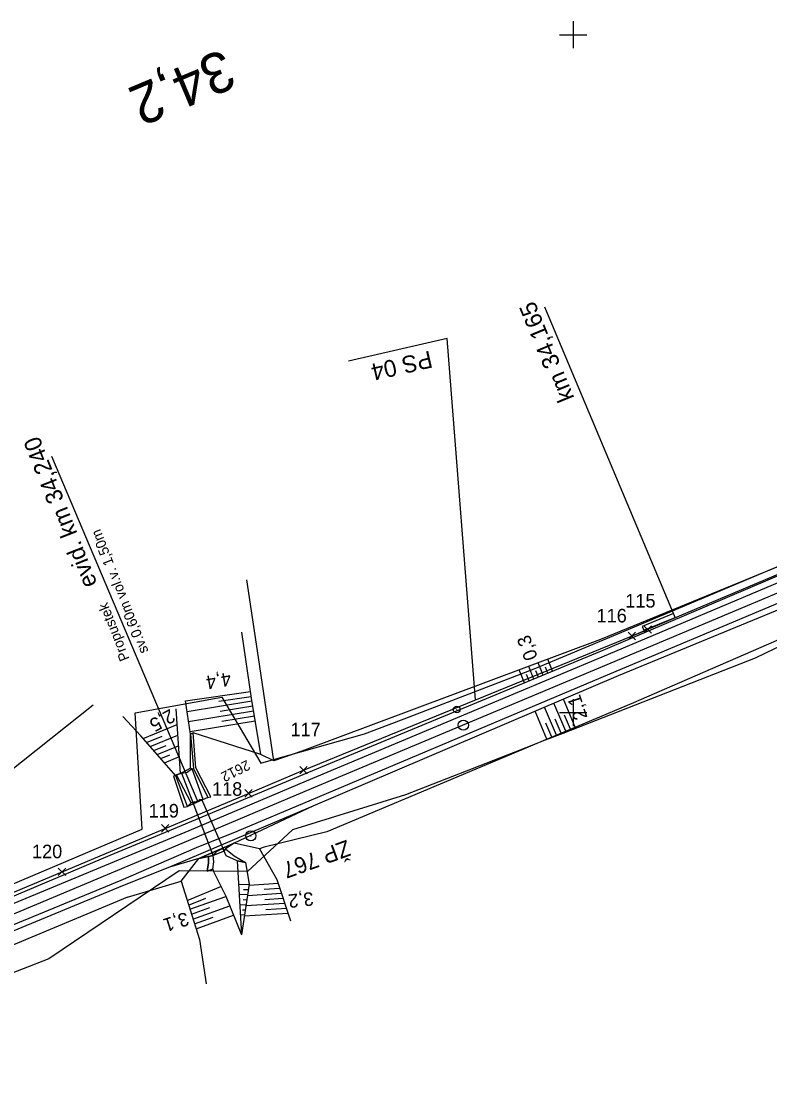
# Model space of a CAD drawing. Extents: x -805730 to -804640, y -1150889 to -1150366.
# Drawn here: x -805081.4 to -804971, y -1150654 to -1150498 of the extents above; entities that cross this region are included whole.
import ezdxf

# ---------------------------------------------------------------- set-up
doc = ezdxf.new("R2010")
doc.units = 0
for name, color, linetype in [('0381KM032-037P - Vrstva 1', 7, 'Continuous'), ('0381KM032-037P - Vrstva 16', 7, 'Continuous'), ('0381KM032-037P - Vrstva 17', 7, 'Continuous'), ('0381KM032-037P - Vrstva 19', 7, 'Continuous'), ('0381KM032-037P - Vrstva 4', 7, 'Continuous'), ('0381KM032-037P - Vrstva 48', 7, 'Continuous'), ('0381KM032-037P - Vrstva 49', 7, 'Continuous'), ('0381KM032-037P - Vrstva 57', 7, 'Continuous'), ('0381KM032-037P - Vrstva 7', 7, 'Continuous'), ('0381KM032-037P - Vrstva 9', 7, 'Continuous'), ('Default', 7, 'Continuous'), ('hran DP - hran DP', 7, 'Continuous'), ('krizky_1000 - Vrstva 1', 7, 'Continuous'), ('PSR_C2_2_Lomove_body_Vimperk - Vrstva 60', 7, 'Continuous'), ('PSR_C2_2_trasa_Vimperk - Kabelová trasa', 7, 'Continuous'), ('SOPS', 7, 'Continuous'), ('vyt_sit - stávající', 7, 'Continuous')]:
    doc.layers.add(name, color=color, linetype=linetype)

msp = doc.modelspace()

# ---------------------------------------------------------------- linework, layer by layer
at = {"layer": '0381KM032-037P - Vrstva 1'}
for points in [[(-804910.33, -1150557.31), (-804952.12, -1150574.92), (-804994.42, -1150592.71), (-805038.63, -1150611.27), (-805057.71, -1150619.3), (-805074.24, -1150626.27)], [(-805074.24, -1150626.27), (-805091.51, -1150633.48)]]:
    msp.add_lwpolyline(points, dxfattribs=at)
at = {"layer": '0381KM032-037P - Vrstva 16'}
for points in [[(-805053.78, -1150621.21), (-805053.78, -1150622.18), (-805053.99, -1150623.39), (-805053.13, -1150623.09), (-805053, -1150622.04), (-805053.1, -1150621.07), (-805053.78, -1150621.21)], [(-805051.5, -1150620.47), (-805051.28, -1150620.09), (-805050.01, -1150621.11), (-805048.33, -1150622.13), (-805049.58, -1150621.86), (-805051.2, -1150621.14), (-805051.5, -1150620.47)]]:
    msp.add_lwpolyline(points, dxfattribs=at)
at = {"layer": '0381KM032-037P - Vrstva 17'}
for points in [[(-804868.16, -1150549.89), (-804869.02, -1150549.09), (-804889.78, -1150557.12), (-804908.89, -1150563.18), (-804949.8, -1150580.61), (-804991.45, -1150598.69), (-805036.34, -1150617.58)], [(-804906.51, -1150551), (-804923.2, -1150557.6), (-804942.52, -1150566.83), (-804953.3, -1150571.71), (-804995.99, -1150589.23), (-805040.03, -1150605.68), (-805044.15, -1150607.13)], [(-805044.15, -1150607.13), (-805046.42, -1150591.86), (-805048.16, -1150580.41)], [(-805070.8, -1150598.9), (-805121.06, -1150638.84), (-805152.76, -1150646.7), (-805170.92, -1150650.08), (-805194.39, -1150650.05), (-805213.2, -1150651.26), (-805221.79, -1150652.33), (-805228.79, -1150654.03)]]:
    msp.add_lwpolyline(points, dxfattribs=at)
at = {"layer": '0381KM032-037P - Vrstva 19'}
for p, q in [((-805076.95, -1150562.18), (-805055.39, -1150613.19)), ((-805056.34, -1150613.34), (-805058.5, -1150609.19)), ((-805054.78, -1150612.85), (-805056.06, -1150613.31)), ((-805053.1, -1150621.07), (-805056.06, -1150613.31)), ((-805054.78, -1150612.85), (-805051.5, -1150620.47)), ((-805051.5, -1150620.47), (-805053.1, -1150621.07))]:
    msp.add_line(p, q, dxfattribs=at)
for points in [[(-805056.22, -1150608.31), (-805056.45, -1150608.2), (-805056.44, -1150603.21)], [(-805053.89, -1150612.54), (-805053.47, -1150612.44), (-805055.64, -1150608.13), (-805056.05, -1150602.98), (-805056.44, -1150603.21), (-805056.02, -1150608.26)], [(-805056.45, -1150608.2), (-805056.99, -1150608.48), (-805057.93, -1150608.98), (-805058.5, -1150609.19)], [(-805054.6, -1150612.84), (-805056.22, -1150608.31), (-805056.92, -1150608.82), (-805057.71, -1150609)], [(-805056.22, -1150608.31), (-805056.02, -1150608.26), (-805053.89, -1150612.54), (-805056.9, -1150613.84)], [(-805056.06, -1150613.31), (-805057.71, -1150609), (-805058.5, -1150609.19), (-805058.59, -1150609.33), (-805058.96, -1150609.37), (-805057.41, -1150613.95), (-805056.9, -1150613.84), (-805058.59, -1150609.33)], [(-805055.86, -1150613.18), (-805056.06, -1150613.31), (-805056.34, -1150613.34), (-805056.9, -1150613.84)], [(-805054.6, -1150612.84), (-805054.78, -1150612.85), (-805055.1, -1150612.83)], [(-805055.21, -1150621.51), (-805053.78, -1150621.21), (-805055.21, -1150621.51), (-805050.01, -1150619.25), (-805051.28, -1150620.09), (-805051.5, -1150620.47), (-805051.69, -1150620.12)], [(-805053.78, -1150621.21), (-805053.1, -1150621.07), (-805052.93, -1150620.83)]]:
    msp.add_lwpolyline(points, dxfattribs=at)
for centre, major_axis, ratio, start_param, end_param in [((-805055.48, -1150613.01), (0.389, 0.172), 0.155868, 3.060843, 6.493994), ((-805052.24, -1150620.62), (-0.751, -0.434), 0.315901, 3.723079, 5.657425)]:
    msp.add_ellipse(centre, major_axis=major_axis, ratio=ratio, start_param=start_param, end_param=end_param, dxfattribs=at)
at = {"layer": '0381KM032-037P - Vrstva 4'}
for points in [[(-804864.42, -1150538.53), (-804893.06, -1150548.77), (-804911.6, -1150556.2), (-804952.82, -1150573.68), (-804994.86, -1150591.44), (-805039.39, -1150610.13), (-805056.71, -1150617.44), (-805097.6, -1150634.39)], [(-804872.17, -1150539.66), (-804893.72, -1150547.52), (-804911.96, -1150555), (-804952.93, -1150572.63), (-804995.29, -1150590.69), (-805039.86, -1150609.18), (-805057.83, -1150616.69), (-805068.36, -1150621.07), (-805097.92, -1150633.57)], [(-804862.73, -1150542.41), (-804863.39, -1150541.46), (-804892.29, -1150551.48), (-804910.22, -1150558.86), (-804951.61, -1150576.23), (-804993.7, -1150593.96), (-805038.63, -1150612.92), (-805049.62, -1150617.53), (-805055.59, -1150619.94), (-805066.74, -1150624.75), (-805096.44, -1150637.01)], [(-804864.94, -1150543.15), (-804869.59, -1150544.8), (-804891.93, -1150552.26), (-804909.8, -1150559.87), (-804951.24, -1150577.2), (-804993.38, -1150594.6), (-805038.39, -1150613.8), (-805059.54, -1150622.79), (-805066.49, -1150625.57), (-805096.25, -1150637.87)]]:
    msp.add_lwpolyline(points, dxfattribs=at)
at = {"layer": '0381KM032-037P - Vrstva 48'}
for p, q in [((-805004.43, -1150594.48), (-805005.15, -1150592.66)), ((-805003.04, -1150593.91), (-805003.74, -1150592.13)), ((-805007.2, -1150595.63), (-805007.96, -1150593.7)), ((-805006.51, -1150595.34), (-805006.88, -1150594.39)), ((-805005.82, -1150595.05), (-805006.56, -1150593.18)), ((-805005.12, -1150594.77), (-805005.49, -1150593.84)), ((-805003.74, -1150594.19), (-805004.09, -1150593.29)), ((-805047.61, -1150596.92), (-805057.19, -1150598.31)), ((-805047.5, -1150597.67), (-805052.29, -1150598.36)), ((-805047.4, -1150598.32), (-805056.95, -1150599.89)), ((-805047.27, -1150599.06), (-805052.05, -1150599.84)), ((-805002.47, -1150603.33), (-805004.21, -1150599.21)), ((-805001.09, -1150602.75), (-805002.83, -1150598.63)), ((-804999.71, -1150602.17), (-805001.45, -1150598.04)), ((-805047.15, -1150599.8), (-805056.72, -1150601.37)), ((-805047.02, -1150600.54), (-805051.82, -1150601.32)), ((-805003.86, -1150603.91), (-805005.59, -1150599.8)), ((-805000.4, -1150602.46), (-805001.27, -1150600.4)), ((-805063.45, -1150603.82), (-805058.4, -1150601.75)), ((-805046.9, -1150601.28), (-805056.5, -1150602.85)), ((-805003.17, -1150603.62), (-805004.03, -1150601.56)), ((-805001.78, -1150603.04), (-805002.65, -1150600.98)), ((-805062.93, -1150604.42), (-805060.64, -1150603.48)), ((-805062.4, -1150605.02), (-805058.3, -1150603.33)), ((-805061.88, -1150605.61), (-805060.06, -1150604.86)), ((-805061.35, -1150606.21), (-805058.2, -1150604.91)), ((-805060.83, -1150606.8), (-805059.49, -1150606.25)), ((-805060.3, -1150607.4), (-805058.09, -1150606.49)), ((-805056.95, -1150627.71), (-805051.95, -1150625.67)), ((-805047.79, -1150625.42), (-805049.38, -1150625.34)), ((-805043.49, -1150625.24), (-805047.8, -1150625.5)), ((-805056.72, -1150628.43), (-805054.17, -1150627.38)), ((-805056.53, -1150629.02), (-805051.22, -1150627.12)), ((-805048.02, -1150626.91), (-805049.29, -1150626.85)), ((-805047.91, -1150626.17), (-805048.62, -1150626.13)), ((-805043.02, -1150626.71), (-805048.04, -1150627.02)), ((-805043.25, -1150625.97), (-805045.59, -1150626.11)), ((-805042.78, -1150627.45), (-805045.47, -1150627.61)), ((-805056.31, -1150629.74), (-805053.62, -1150628.78)), ((-805056.08, -1150630.46), (-805050.66, -1150628.52)), ((-805048.26, -1150628.4), (-805049.2, -1150628.36)), ((-805048.14, -1150627.66), (-805048.69, -1150627.63)), ((-805042.54, -1150628.18), (-805048.28, -1150628.53)), ((-805042.3, -1150628.92), (-805045.35, -1150629.11)), ((-805055.86, -1150631.17), (-805053.12, -1150630.19)), ((-805055.63, -1150631.89), (-805050.1, -1150629.91)), ((-805048.49, -1150629.89), (-805049.11, -1150629.86)), ((-805048.37, -1150629.15), (-805048.77, -1150629.13)), ((-805042.06, -1150629.66), (-805048.51, -1150630.05))]:
    msp.add_line(p, q, dxfattribs=at)
at = {"layer": '0381KM032-037P - Vrstva 49'}
for p, q in [((-805056.44, -1150603.21), (-805057.2, -1150598.28)), ((-805057.93, -1150608.98), (-805058.55, -1150599.44)), ((-805056.05, -1150602.98), (-805056.44, -1150603.21)), ((-805044.15, -1150607.13), (-805046.07, -1150606.17)), ((-805049.58, -1150621.86), (-805048.94, -1150632.8)), ((-805049.58, -1150621.86), (-805048.33, -1150622.13))]:
    msp.add_line(p, q, dxfattribs=at)
for points in [[(-804871.36, -1150538.86), (-804872.17, -1150539.66), (-804893.72, -1150547.52), (-804911.96, -1150555), (-804952.93, -1150572.63), (-804995.29, -1150590.69), (-805039.86, -1150609.18), (-805057.83, -1150616.69), (-805068.36, -1150621.07), (-805097.92, -1150633.57)], [(-804906.51, -1150551), (-804923.2, -1150557.6), (-804942.52, -1150566.83), (-804953.3, -1150571.71), (-804995.99, -1150589.23), (-805040.03, -1150605.68), (-805044.15, -1150607.13)], [(-804889.78, -1150557.12), (-804908.89, -1150563.18), (-804949.8, -1150580.61), (-804991.45, -1150598.69), (-805036.34, -1150617.58)], [(-804909.8, -1150559.87), (-804951.24, -1150577.2), (-804993.38, -1150594.6), (-805038.39, -1150613.8), (-805050.01, -1150619.25), (-805055.21, -1150621.51), (-805059.54, -1150622.79), (-805066.49, -1150625.57), (-805096.25, -1150637.87)], [(-805046.07, -1150606.17), (-805047.47, -1150597.89), (-805048.87, -1150588.15)], [(-805070.8, -1150598.9), (-805121.06, -1150638.84), (-805152.76, -1150646.7), (-805170.92, -1150650.08), (-805194.39, -1150650.05), (-805213.2, -1150651.26), (-805221.79, -1150652.33), (-805228.79, -1150654.03)], [(-805058.59, -1150609.33), (-805063.79, -1150603.44), (-805066.42, -1150600.59)], [(-805046.07, -1150606.17), (-805056.05, -1150602.98)], [(-805058.59, -1150609.33), (-805058.5, -1150609.19), (-805057.93, -1150608.98)], [(-805036.34, -1150617.58), (-805045.56, -1150619.85), (-805046.28, -1150620.1), (-805050.01, -1150619.25)], [(-805053.13, -1150623.09), (-805053.99, -1150623.39), (-805053.78, -1150622.18), (-805053.78, -1150621.21), (-805055.21, -1150621.51)], [(-805046.28, -1150620.1), (-805043.7, -1150624.61), (-805041.72, -1150630.72)], [(-805065.73, -1150627.22), (-805057.84, -1150624.88), (-805055.21, -1150621.51)], [(-805048.33, -1150622.13), (-805047.78, -1150625.31), (-805048.94, -1150632.8)], [(-805053.13, -1150623.09), (-805053.07, -1150623.46), (-805051.23, -1150627.1), (-805048.94, -1150632.8)], [(-805057.84, -1150624.88), (-805055.13, -1150633.48), (-805054.13, -1150640.03)], [(-805065.73, -1150627.22), (-805095.53, -1150639.67)]]:
    msp.add_lwpolyline(points, dxfattribs=at)
at = {"layer": '0381KM032-037P - Vrstva 7'}
msp.add_line((-805017.22, -1150599.55), (-805017.12, -1150599.55), dxfattribs=at)
for centre, radius in [((-805017.17, -1150599.55), 0.5), ((-805016.2, -1150601.85), 0.75)]:
    msp.add_circle(centre, radius, dxfattribs=at)
at = {"layer": '0381KM032-037P - Vrstva 9'}
for p, q in [((-805004.24, -1150540.13), (-804985.09, -1150585.68)), ((-804985.2, -1150585.4), (-804985.43, -1150584.85)), ((-804985.2, -1150585.4), (-804989.83, -1150587.31)), ((-804989.6, -1150587.86), (-804984.97, -1150585.96)), ((-804984.97, -1150585.96), (-804985.2, -1150585.4)), ((-804989.83, -1150587.31), (-804989.6, -1150587.86))]:
    msp.add_line(p, q, dxfattribs=at)
at = {"layer": 'hran DP - hran DP'}
for p, q in [((-804981, -1150583.16), (-804968.41, -1150577.86)), ((-804951.89, -1150581.61), (-804973.16, -1150591.99)), ((-804993.4, -1150588.37), (-804981, -1150583.16)), ((-805005.74, -1150593.57), (-804993.4, -1150588.37)), ((-804973.16, -1150591.99), (-805001.53, -1150603.08)), ((-805024.92, -1150600.92), (-805005.74, -1150593.57)), ((-805064.61, -1150600.03), (-805051.81, -1150597.72)), ((-805051.81, -1150597.72), (-805046.06, -1150607.46)), ((-805063.58, -1150617.18), (-805064.61, -1150600.03)), ((-805030.76, -1150603.16), (-805024.92, -1150600.92)), ((-805043.88, -1150606.84), (-805030.76, -1150603.16)), ((-805001.53, -1150603.08), (-805004.51, -1150604.24)), ((-805006.96, -1150605.2), (-805008.86, -1150605.94)), ((-805004.51, -1150604.24), (-805006.96, -1150605.2)), ((-805046.06, -1150607.46), (-805043.88, -1150606.84)), ((-805008.86, -1150605.94), (-805024.72, -1150612.14)), ((-805024.72, -1150612.14), (-805041.4, -1150617.28)), ((-805066.7, -1150618.51), (-805063.58, -1150617.18)), ((-805041.4, -1150617.28), (-805048.02, -1150623.43)), ((-805096.7, -1150631.27), (-805066.7, -1150618.51)), ((-805058.1, -1150623.37), (-805077.33, -1150636.32)), ((-805048.02, -1150623.43), (-805058.1, -1150623.37)), ((-805077.33, -1150636.32), (-805095.21, -1150643.26))]:
    msp.add_line(p, q, dxfattribs=at)
at = {"layer": 'krizky_1000 - Vrstva 1'}
for points in [[(-805000, -1150498), (-805000, -1150502)], [(-805002, -1150500), (-804998, -1150500)], [(-805000, -1150598), (-805000, -1150602)], [(-805002, -1150600), (-804998, -1150600)]]:
    msp.add_lwpolyline(points, dxfattribs=at)
at = {"layer": 'PSR_C2_2_Lomove_body_Vimperk - Vrstva 60'}
for p, q in [((-804991.9, -1150589.26), (-804990.8, -1150588.16)), ((-804990.8, -1150589.26), (-804991.9, -1150588.16)), ((-804989.56, -1150588.31), (-804988.46, -1150587.21)), ((-804988.46, -1150588.31), (-804989.56, -1150587.21)), ((-805040.34, -1150609.05), (-805039.24, -1150607.95)), ((-805039.24, -1150609.05), (-805040.34, -1150607.95)), ((-805048.45, -1150612.47), (-805047.35, -1150611.37)), ((-805047.35, -1150612.47), (-805048.45, -1150611.37)), ((-805060.72, -1150617.63), (-805059.62, -1150616.53)), ((-805059.62, -1150617.63), (-805060.72, -1150616.53)), ((-805075.95, -1150624.05), (-805074.85, -1150622.95)), ((-805074.85, -1150624.05), (-805075.95, -1150622.95))]:
    msp.add_line(p, q, dxfattribs=at)
at = {"layer": 'PSR_C2_2_trasa_Vimperk - Kabelová trasa'}
for points in [[(-804861.61, -1150536.05), (-804874.49, -1150540.07), (-804895.8, -1150547.79), (-804932.46, -1150563.38), (-804958.05, -1150574.66), (-804991.35, -1150588.71)], [(-805122.45, -1150641.59), (-805112.53, -1150638.37), (-805102.25, -1150634.46), (-805084.03, -1150627.11), (-805075.4, -1150623.5), (-805060.17, -1150617.08), (-805047.9, -1150611.92), (-805039.79, -1150608.5), (-804989.01, -1150587.76)]]:
    msp.add_lwpolyline(points, dxfattribs=at)
at = {"layer": 'SOPS'}
msp.add_lwpolyline([(-805014.4, -1150598.13), (-805018.6, -1150544.84), (-805033.13, -1150548.15)], dxfattribs=at)
at = {"layer": 'vyt_sit - stávající'}
msp.add_line((-805047.59, -1150618.19), (-805047.49, -1150618.19), dxfattribs=at)
msp.add_circle((-805047.55, -1150618.19), 0.756, dxfattribs=at)

# ---------------------------------------------------------------- texts
at = {"layer": '0381KM032-037P - Vrstva 19'}
for s, height, p in [('evid. km 34,240', 2.5, (-805070.16, -1150581.01)), ('sv.0,60m vol.v. 1,50m', 1.5, (-805062.62, -1150590.96)), ('Propustek', 1.5, (-805065.41, -1150592.06))]:
    msp.add_text(s, height=height, rotation=111.5275, dxfattribs=at).set_placement(p)
at = {"layer": '0381KM032-037P - Vrstva 48'}
for s, rotation, p in [('0,3', 110.4812, (-805005.19, -1150591.87)), ('4,4', 189.5991, (-805050.63, -1150594.02)), ('2,1', 108.1045, (-804997.87, -1150600.72)), ('2,5', 208.7064, (-805059.44, -1150599.4)), ('3,2', 186.1394, (-805038.41, -1150626.45)), ('3,1', 197.4468, (-805057.08, -1150629.39))]:
    msp.add_text(s, height=2, rotation=rotation, dxfattribs=at).set_placement(p)
at = {"layer": '0381KM032-037P - Vrstva 57'}
msp.add_text('2612', height=1.5, rotation=206.8307, dxfattribs=at).set_placement((-805048.13, -1150606.95))
at = {"layer": '0381KM032-037P - Vrstva 7'}
msp.add_text('34,2', height=6, rotation=202.7734, dxfattribs=at).set_placement((-805051.6, -1150502))
at = {"layer": '0381KM032-037P - Vrstva 9'}
msp.add_text('km 34,165', height=2.5, rotation=112.3772, dxfattribs=at).set_placement((-804999.79, -1150553.58))
at = {"layer": 'Default'}
for s, p in [('115', (-804992.31, -1150584.51)), ('116', (-804996.55, -1150586.7)), ('117', (-805041.7, -1150603.5)), ('118', (-805053.27, -1150612.28)), ('119', (-805062.62, -1150615.48)), ('120', (-805079.83, -1150621.49))]:
    msp.add_text(s, height=2, dxfattribs=at).set_placement(p)
at = {"layer": 'SOPS'}
msp.add_text('PS 04', height=2.5, rotation=192.874, dxfattribs=at).set_placement((-805021.12, -1150546.6))
at = {"layer": 'vyt_sit - stávající'}
msp.add_text('ŽP 767', height=2.4, rotation=200, dxfattribs=at).set_placement((-805033.38, -1150618.73))

doc.saveas('drawing.dxf')
